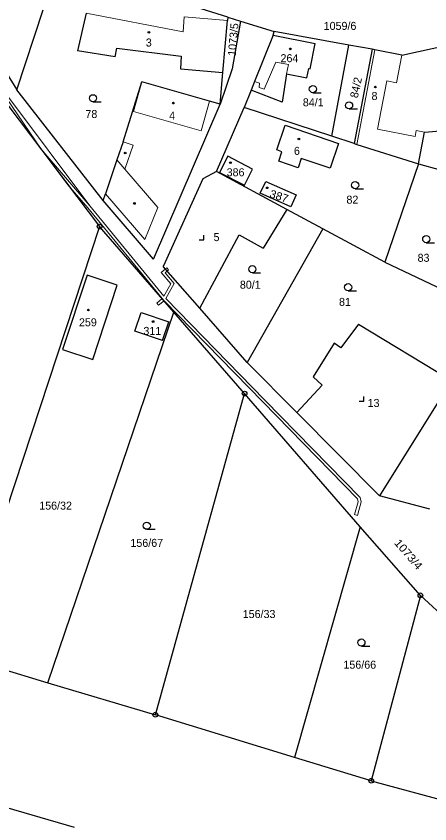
# Model space of a CAD drawing. Extents: x -694609 to -690140, y -1033292 to -1029794.
# Drawn here: x -693215.9 to -693128, y -1031416.8 to -1031245.2 of the extents above; entities that cross this region are included whole.
import ezdxf
from ezdxf.enums import TextEntityAlignment as Align

# ---------------------------------------------------------------- set-up
doc = ezdxf.new("R2010")
doc.units = 0
doc.header["$LTSCALE"] = 0.68
for name, color, linetype, lineweight in [('1', 7, 'Continuous', 25), ('13', 7, 'Continuous', 13), ('3', 7, 'Continuous', 25), ('4', 7, 'Continuous', 13), ('5', 7, 'Continuous', 25), ('8', 7, 'Continuous', 25)]:
    doc.layers.add(name, color=color, linetype=linetype, lineweight=lineweight)
doc.layers.add('2', color=7, linetype='Continuous')

msp = doc.modelspace()

# ---------------------------------------------------------------- linework, layer by layer
at = {"layer": '1'}
for p, q in [((-693234.03, -1031231.76), (-693215.77, -1031260.84)), ((-693170.92, -1031245.42), (-693199.19, -1031236.57)), ((-693215.77, -1031260.84), (-693210.16, -1031243.87)), ((-693201.04, -1031244.57), (-693202.88, -1031252.55)), ((-693172.02, -1031257.19), (-693171.01, -1031246.12)), ((-693170.92, -1031245.42), (-693171.01, -1031246.12)), ((-693170.92, -1031245.42), (-693168.24, -1031246.26)), ((-693168.24, -1031246.26), (-693161.09, -1031248.5)), ((-693161.3, -1031249.23), (-693165.23, -1031259.09)), ((-693161.3, -1031249.23), (-693161.09, -1031248.5)), ((-693161.3, -1031249.23), (-693152.38, -1031251)), ((-693145.24, -1031251.36), (-693161.09, -1031248.5)), ((-693153.45, -1031256.39), (-693152.38, -1031251)), ((-693148.86, -1031270.72), (-693145.24, -1031251.36)), ((-693140.28, -1031252.25), (-693145.24, -1031251.36)), ((-693133.94, -1031253.47), (-693123.76, -1031251.26)), ((-693194.91, -1031253.88), (-693202.88, -1031252.55)), ((-693194.91, -1031253.88), (-693194.55, -1031252.01)), ((-693194.55, -1031252.01), (-693180.82, -1031253.72)), ((-693140.28, -1031252.25), (-693144.07, -1031272.29)), ((-693139.68, -1031252.36), (-693140.28, -1031252.25)), ((-693133.94, -1031253.47), (-693139.68, -1031252.36)), ((-693180.82, -1031253.72), (-693180.99, -1031256.4)), ((-693180.99, -1031256.4), (-693172.02, -1031257.19)), ((-693154.14, -1031258.35), (-693153.74, -1031256.34)), ((-693153.74, -1031256.34), (-693153.45, -1031256.39)), ((-693172.57, -1031263.94), (-693172.02, -1031257.19)), ((-693158.46, -1031257.5), (-693159.39, -1031263.47)), ((-693158.46, -1031257.5), (-693154.14, -1031258.35)), ((-693193.19, -1031271.88), (-693189.2, -1031259.18)), ((-693174.8, -1031263.3), (-693189.2, -1031259.18)), ((-693165.23, -1031259.09), (-693165.97, -1031260.95)), ((-693197.43, -1031284.36), (-693215.77, -1031260.84)), ((-693165.97, -1031260.95), (-693167.44, -1031264.64)), ((-693159.39, -1031263.47), (-693165.97, -1031260.95)), ((-693172.57, -1031263.94), (-693174.8, -1031263.3)), ((-693217.72, -1031264.13), (-693198.18, -1031289.92)), ((-693186.74, -1031296.84), (-693172.57, -1031263.94)), ((-693173.32, -1031278.22), (-693167.44, -1031264.64)), ((-693148.86, -1031270.72), (-693167.44, -1031264.64)), ((-693160.52, -1031273.63), (-693158.77, -1031268.39)), ((-693158.77, -1031268.39), (-693147.43, -1031272.29)), ((-693130.41, -1031276.57), (-693129.11, -1031269.84)), ((-693129.11, -1031269.84), (-693124.97, -1031269.5)), ((-693193.19, -1031271.88), (-693194.49, -1031275.71)), ((-693144.07, -1031272.29), (-693148.86, -1031270.72)), ((-693159.43, -1031274.01), (-693160.52, -1031273.63)), ((-693147.43, -1031272.29), (-693149.21, -1031277.51)), ((-693144.07, -1031272.29), (-693143.51, -1031272.48)), ((-693143.51, -1031272.48), (-693130.41, -1031276.57)), ((-693170.95, -1031274.95), (-693172.69, -1031278.4)), ((-693165.66, -1031277.7), (-693170.95, -1031274.95)), ((-693160.08, -1031275.99), (-693159.43, -1031274.01)), ((-693155.32, -1031275.42), (-693155.98, -1031277.4)), ((-693149.21, -1031277.51), (-693155.32, -1031275.42)), ((-693194.49, -1031275.71), (-693196.94, -1031282.93)), ((-693155.98, -1031277.4), (-693160.08, -1031275.99)), ((-693130.41, -1031276.57), (-693137.56, -1031297.47)), ((-693130.41, -1031276.57), (-693125.78, -1031277.83)), ((-693173.32, -1031278.22), (-693176.25, -1031279.77)), ((-693158.39, -1031286.26), (-693173.32, -1031278.22)), ((-693176.25, -1031279.77), (-693184.25, -1031297.45)), ((-693164.03, -1031282.82), (-693162.84, -1031280.3)), ((-693162.84, -1031280.3), (-693156.42, -1031283.18)), ((-693197.43, -1031284.36), (-693196.94, -1031282.93)), ((-693157.56, -1031285.72), (-693164.03, -1031282.82)), ((-693156.42, -1031283.18), (-693157.56, -1031285.72)), ((-693186.74, -1031296.84), (-693197.43, -1031284.36)), ((-693158.39, -1031286.26), (-693163.44, -1031294.52)), ((-693150.76, -1031290.37), (-693158.39, -1031286.26)), ((-693198.18, -1031289.92), (-693228.28, -1031381.08)), ((-693182.42, -1031308.05), (-693198.18, -1031289.92)), ((-693150.76, -1031290.37), (-693166.82, -1031318.76)), ((-693137.56, -1031297.47), (-693150.76, -1031290.37)), ((-693176.91, -1031307.25), (-693168.52, -1031291.63)), ((-693168.52, -1031291.63), (-693163.44, -1031294.52)), ((-693184.25, -1031297.45), (-693184.7, -1031298.37)), ((-693137.56, -1031297.47), (-693117.89, -1031306.85)), ((-693176.91, -1031307.25), (-693184.7, -1031298.37)), ((-693200.85, -1031300.24), (-693206.05, -1031316)), ((-693194.43, -1031302.36), (-693200.85, -1031300.24)), ((-693199.63, -1031318.12), (-693194.43, -1031302.36)), ((-693209.17, -1031386.78), (-693182.42, -1031308.05)), ((-693190.67, -1031312.12), (-693189.32, -1031308.14)), ((-693189.32, -1031308.14), (-693183.45, -1031310.14)), ((-693167.36, -1031325.38), (-693182.42, -1031308.05)), ((-693166.82, -1031318.76), (-693176.91, -1031307.25)), ((-693184.8, -1031314.11), (-693183.45, -1031310.14)), ((-693143.16, -1031310.61), (-693146.91, -1031315.69)), ((-693143.16, -1031310.61), (-693123.43, -1031322.59)), ((-693184.8, -1031314.11), (-693190.67, -1031312.12)), ((-693148.33, -1031314.66), (-693152.79, -1031321.84)), ((-693146.91, -1031315.69), (-693148.33, -1031314.66)), ((-693206.05, -1031316), (-693199.63, -1031318.12)), ((-693156.26, -1031329.39), (-693166.82, -1031318.76)), ((-693152.79, -1031321.84), (-693150.91, -1031323.56)), ((-693156.26, -1031329.39), (-693150.91, -1031323.56)), ((-693123.43, -1031322.59), (-693138.69, -1031347.09)), ((-693186.34, -1031393.6), (-693167.36, -1031325.38)), ((-693142.78, -1031353.67), (-693167.36, -1031325.38)), ((-693138.69, -1031347.09), (-693156.26, -1031329.39)), ((-693127.97, -1031349.93), (-693138.69, -1031347.09)), ((-693142.78, -1031353.67), (-693156.77, -1031402.64)), ((-693130.01, -1031368.23), (-693142.78, -1031353.67)), ((-693130.01, -1031368.23), (-693140.45, -1031407.6)), ((-693114.88, -1031382.29), (-693130.01, -1031368.23)), ((-693228.28, -1031381.08), (-693209.17, -1031386.78)), ((-693209.17, -1031386.78), (-693186.34, -1031393.6)), ((-693156.77, -1031402.64), (-693186.34, -1031393.6)), ((-693140.45, -1031407.6), (-693156.77, -1031402.64)), ((-693237.08, -1031407.73), (-693203.62, -1031417.48)), ((-693140.45, -1031407.6), (-693090.02, -1031421.29))]:
    msp.add_line(p, q, dxfattribs=at)
for points in [[(-693168.24, -1031246.26), (-693169.98, -1031256.38), (-693172.57, -1031263.94)], [(-693172.69, -1031278.4), (-693167.39, -1031281.13), (-693165.66, -1031277.7)]]:
    msp.add_lwpolyline(points, dxfattribs=at)
at = {"layer": '13'}
for points in [[(-693200.24, -1031285.53), (-693217.75, -1031262.13), (-693224.52, -1031252.92), (-693230.99, -1031242.92), (-693236.58, -1031234.54), (-693237.06, -1031234.87), (-693227.67, -1031248.57), (-693224.82, -1031253.03), (-693217.95, -1031262.64), (-693210.63, -1031273.49)], [(-693184.89, -1031305.21), (-693184.49, -1031305.66), (-693163.48, -1031327.16), (-693143.36, -1031347.76), (-693143.21, -1031348.37), (-693143.98, -1031351.09), (-693143.4, -1031351.25), (-693142.59, -1031348.37), (-693142.82, -1031347.46), (-693163.06, -1031326.74), (-693184.09, -1031305.2), (-693182.34, -1031302.01), (-693184.25, -1031299.74), (-693183.82, -1031299.37), (-693184.22, -1031298.92), (-693185.09, -1031299.67), (-693183.06, -1031302.09), (-693184.51, -1031304.72), (-693200.24, -1031285.53), (-693210.63, -1031273.49), (-693204.93, -1031281.01), (-693200.7, -1031285.91)], [(-693184.22, -1031298.92), (-693183.82, -1031299.37), (-693183.51, -1031299.1), (-693183.91, -1031298.66)], [(-693186.03, -1031306.14), (-693185.65, -1031306.6), (-693184.49, -1031305.66), (-693184.89, -1031305.21)]]:
    msp.add_lwpolyline(points, close=True, dxfattribs=at)
at = {"layer": '3'}
for p, q in [((-693152.863, -1031261.47), (-693151.113, -1031261.47)), ((-693199.593, -1031263.4), (-693197.843, -1031263.4)), ((-693145.153, -1031264.92), (-693143.403, -1031264.92)), ((-693143.873, -1031281.86), (-693142.123, -1031281.86)), ((-693128.773, -1031293.33), (-693127.023, -1031293.33)), ((-693165.723, -1031299.7), (-693163.973, -1031299.7)), ((-693145.363, -1031303.53), (-693143.613, -1031303.53)), ((-693188.153, -1031354.2), (-693186.403, -1031354.2)), ((-693142.533, -1031379), (-693140.783, -1031379))]:
    msp.add_line(p, q, dxfattribs=at)
for points in [[(-693177.041, -1031292.75), (-693176.04, -1031292.75), (-693176.04, -1031291.75)], [(-693143.021, -1031327), (-693142.02, -1031327), (-693142.02, -1031326)]]:
    msp.add_lwpolyline(points, dxfattribs=at)
for centre in [(-693152.8629, -1031260.7198), (-693199.5929, -1031262.6498), (-693145.1529, -1031264.1698), (-693143.8729, -1031281.1098), (-693128.7729, -1031292.5798), (-693165.7229, -1031298.9498), (-693145.3629, -1031302.7798), (-693188.1529, -1031353.4498), (-693142.5329, -1031378.2498)]:
    msp.add_circle(centre, 0.75, dxfattribs=at)
at = {"layer": '4'}
for p, q in [((-693180.43, -1031248.51), (-693201.04, -1031244.57)), ((-693180.2, -1031245.37), (-693180.43, -1031248.51)), ((-693171.01, -1031246.12), (-693180.2, -1031245.37)), ((-693139.68, -1031252.36), (-693143.51, -1031272.48)), ((-693163.18, -1031260.71), (-693160.71, -1031254.96)), ((-693160.71, -1031254.96), (-693158.06, -1031255.48)), ((-693158.06, -1031255.48), (-693158.46, -1031257.5)), ((-693191, -1031265.48), (-693189.2, -1031259.18)), ((-693174.8, -1031263.3), (-693176.6, -1031269.59)), ((-693176.6, -1031269.59), (-693191, -1031265.48)), ((-693130.88, -1031269.49), (-693131.12, -1031270.77)), ((-693129.11, -1031269.84), (-693130.88, -1031269.49)), ((-693191.07, -1031272.64), (-693193.19, -1031271.88)), ((-693192.79, -1031277.69), (-693191.07, -1031272.64)), ((-693192.79, -1031277.69), (-693194.49, -1031275.71)), ((-693185.79, -1031285.85), (-693192.79, -1031277.69)), ((-693188.59, -1031292.68), (-693196.94, -1031282.93)), ((-693188.59, -1031292.68), (-693185.79, -1031285.85))]:
    msp.add_line(p, q, dxfattribs=at)
for points in [[(-693131.12, -1031270.77), (-693139.13, -1031269.22), (-693137.14, -1031258.96), (-693135.08, -1031259.36), (-693133.94, -1031253.47)], [(-693163.18, -1031260.71), (-693164.28, -1031260.38), (-693164.23, -1031259.48), (-693165.23, -1031259.09)]]:
    msp.add_lwpolyline(points, dxfattribs=at)
at = {"layer": '5'}
for centre in [(-693187.7168, -1031248.6392), (-693157.6668, -1031252.1592), (-693139.5768, -1031260.2692), (-693182.5068, -1031263.6792), (-693155.8368, -1031271.2992), (-693192.7368, -1031274.2892), (-693170.3768, -1031276.3192), (-693162.5668, -1031281.6792), (-693190.7768, -1031284.9892), (-693200.5768, -1031307.6292), (-693186.8068, -1031310.0692)]:
    msp.add_circle(centre, 0.175, dxfattribs=at)
at = {"layer": '8'}
for centre, radius in [((-693198.18, -1031289.9199), 0.5), ((-693198.18, -1031289.9199), 0.0303), ((-693167.36, -1031325.3799), 0.5), ((-693167.36, -1031325.3799), 0.0303), ((-693130.01, -1031368.2299), 0.5), ((-693130.01, -1031368.2299), 0.0303), ((-693186.34, -1031393.5999), 0.5), ((-693186.34, -1031393.5999), 0.0303), ((-693140.45, -1031407.5999), 0.5), ((-693140.45, -1031407.5999), 0.0303)]:
    msp.add_circle(centre, radius, dxfattribs=at)

# ---------------------------------------------------------------- texts
at = {"layer": '2'}
for s, p in [('1059/6', (-693147.09, -1031248.135)), ('3', (-693187.74, -1031251.665)), ('264', (-693157.839, -1031254.995)), ('8', (-693139.76, -1031263.015)), ('84/1', (-693152.779, -1031264.365)), ('78', (-693199.939, -1031266.845)), ('4', (-693182.77, -1031267.185)), ('6', (-693156.25, -1031274.675)), ('386', (-693169.289, -1031279.225)), ('82', (-693144.459, -1031285.045)), ('5', (-693173.34, -1031292.995)), ('83', (-693129.339, -1031297.385)), ('80/1', (-693166.159, -1031303.105)), ('81', (-693146.039, -1031306.755)), ('259', (-693200.679, -1031311.085)), ('311', (-693186.979, -1031312.915)), ('13', (-693139.959, -1031328.215)), ('156/32', (-693207.54, -1031350.025)), ('156/67', (-693188.16, -1031357.935)), ('156/33', (-693164.29, -1031373.045)), ('156/66', (-693142.89, -1031383.805))]:
    msp.add_text(s, height=1.7, dxfattribs=at).set_placement(p, align=Align.CENTER)
msp.add_text('1073/5', height=1.7, rotation=85, dxfattribs=at).set_placement((-693168.9526, -1031250.2491), align=Align.CENTER)
msp.add_text('84/2', height=1.7, rotation=78, dxfattribs=at).set_placement((-693143.324, -1031262.718))
for s, rotation, width, p in [('387', 342, 1.05, (-693160.3067, -1031284.2669)), ('1073/4', 311, 1.1, (-693133.1832, -1031360.0619))]:
    msp.add_text(s, height=1.7, rotation=rotation, dxfattribs=dict(at, width=width)).set_placement(p, align=Align.CENTER)

doc.saveas('drawing.dxf')
